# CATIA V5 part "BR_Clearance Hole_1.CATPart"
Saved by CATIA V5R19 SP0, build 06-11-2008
Bounding box of the stored display mesh (mm): x 31.683 to 45.357, y -64.65 to -50.65, z -40 to 0
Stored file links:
  C:\Program Files\Dassault Systemes\Power Feature\SampleData\SharedData\BusinessRules\BR_RulesPart\BR_Clearance Hole_1.CATPart
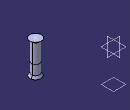
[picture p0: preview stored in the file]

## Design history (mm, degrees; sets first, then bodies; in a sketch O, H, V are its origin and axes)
Set1
  Point1: type OnPlane, Support xy-plane, Direction (1, 0, 0), H 38.52, V -57.65
  Plane1: type Offset, Offset 40, RefPlane xy-plane, reversed
Body1 (main body)
  UdfFeature1 "Clearance Hole": UdfInputSpec1 AxisSystem1, UdfInputSpec2 Project1, UdfInputSpec3 Intersect1, DB 10, L 40 {= Body2.Offset + (Sketch1.length(L11) * (Body2.Offset / Body2.Offset ))}, F1 2, W1 90, F2 3, W2 60, DP 10, TP 25, AS_H 0, AS_D 0, InternalVersion 1, Through true, Threaded false, UIHidden_zDB 5 {= Sketch1.Radius(L1 L8)}, UIHidden_zF1 2, UIHidden_zTP 25
Body2 "UDF_Body"
  AxisSystem1 "MainAxisSystem": origin (38.52, -57.65, 0), X (-0.7542, -0.6566, 0), Y (0.6566, -0.7542, 0), Z (0, 0, 1)
  Project1 "Project": Support Plane1, ToProject vertex [YZ plane of AxisSystem1 | ZX plane of AxisSystem1 | XY plane of AxisSystem1]
  Intersect1 "Intersect": ToIntersect1 edge [ZX plane of AxisSystem1 | YZ plane of AxisSystem1], ToIntersect2 Plane1
  Sketch1 "MainProfileSketch" on ZX plane of AxisSystem1, origin (38.52, -57.65, 0), H (0.7542, 0.6566, 0), V (0, 0, 1)
    axis line L1 (0, 0) -> (0, -40)
    point P2 (5, -37)
    line L2 (5, -37) -> (5, -25)
    point P3 (5, -2)
    line L3 (5, -2) -> (7, 0)
    point P4 (7, 0)
    line L4 (7, 0) -> (7, 0)
    line L5 (7, 0) -> (7, 0)
    line L6 (7, 0) -> (0, 0)
    point P7 (-7, 0)
    point P8 (-5, -2)
    construction line L7 (-5, -2) -> (-7, 0)
    line L8 (5, -2) -> (5, -25)
    construction line L9 (7, 0) -> (0, 0)
    reference projected line E1 through (0, 0) direction (-1, 0) from edge [XY plane of AxisSystem1 | ZX plane of AxisSystem1]
    reference projected line E2 through (0, 0) direction (-1, 0) from edge [XY plane of AxisSystem1 | ZX plane of AxisSystem1]
    reference projected line E3 through (0, 0) direction (-1, 0) from edge [XY plane of AxisSystem1 | ZX plane of AxisSystem1]
    reference projected line E4 through (0, 0) direction (-1, 0) from edge [XY plane of AxisSystem1 | ZX plane of AxisSystem1]
    reference projected line E5 through (0, 0) direction (0, 1) from edge [ZX plane of AxisSystem1 | YZ plane of AxisSystem1]
    line L10 (5, -37) -> (6.7321, -40)
    point P9 (6.7321, -40)
    line L11 (6.7321, -40) -> (0, -40)
    point P11 (-6.7321, -40)
    point P12 (-5, -37)
    construction line L12 (-5, -37) -> (-6.7321, -40)
    reference projected line E6 through (0, 0) direction (-1, 0) from edge [XY plane of AxisSystem1 | ZX plane of AxisSystem1]
    point P13 (0, 30)
    point P14 (5, 25)
    point P15 (5, -25)
    line L13 (5, -25) -> (5, -25)
    point P16 (5, -25)
    point P17 (5, -25)
    angle L3 L7 = 90
    "UIHidden_zDB" L1 L2 = 5 {= Sketch1.Radius(L1 L8)}
    distance E1 L11 = 40 {= Body2.Offset + (Sketch1.length(L11) * (Body2.Offset / Body2.Offset ))}
    "Radius" L1 L8 = 5 {= Body2.DB / 2}
    distance E2 P15 = 25
    length L9 = 7 {= sqrt((Body2.AS_H * Body2.AS_H ) + ((Groove1.top_width / 2 + Groove1.AS_ZR ) * (Groove1.top_width / 2 + Groove1.AS_ZR )))}
    angle L9 L4 = 0 {= atan(Body2.AS_H / (Groove1.top_width / 2 + Groove1.AS_ZR ))}
    distance E6 P3 = 2
    angle L10 L12 = 60
    distance L11 P2 = 3
    length L11 = 6.7321
    distance O P13 = 30
    distance P3 P13 V = 32 {= Sketch1.distance(O P13) + Body2.F1}
    distance O P14 V = 25
    distance P15 P14 = 50 {= Sketch1.distance(O P14 V) + Body2.TP}
    distance P16 P14 = 50
    distance P17 P14 = 50
    coincidence: E3 L4, L1 E5, P13 L1, P14 L8, P15 L8
    symmetry: P4 P7 L1, P3 P8 L1, L3 L7 L1, P9 P11 L1, P2 P12 L1, L10 L12 L1
    perpendicularity: L1 L6, E4 L5
  Groove1 "MainGroove": profile Sketch1, axis Sketch1.L1, angle 360
  Point2 "LimitingAxisSystemOrigin": type OnCurve, Support edge [ZX plane of AxisSystem1 | YZ plane of AxisSystem1], Length 0 {= (Sketch1.length(L11)) * (Body2.Offset / Body2.Offset)}, RefPoint Intersect1
  AxisSystem2 "LimitingAxisSystem": origin (38.52, -57.65, -40), X (-0.7542, -0.6566, 0), Y (0.6566, -0.7542, 0), Z (0, 0, -1)
Relations
  Body2.W1 = Sketch1.angle(L3 L7)
  Body2.F2 = Sketch1.distance(L11 P2)
  Body2.W2 = Sketch1.angle(L10 L12)
  Groove1.top_width = (Sketch1.Radius(L1 L8) * 2) + (2 * tan (Sketch1.angle(L3 L7) / 2) * Sketch1.distance(E6 P3))
  Body2.L = Sketch1.distance(E1 L11)
  rule "AS_ZR":
    /*Rule created by AKNOPP 22.05.2006*/
    Groove1.AS_ZR = Body2.AS_D - Groove1.top_width
    if (Body2.AS_D == 0mm)
    {
    	Groove1.AS_ZR = 0mm
    }
    else
    {
    	Groove1.AS_ZR = (Body2.AS_D / 2) - (Groove1.top_width / 2)
    }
